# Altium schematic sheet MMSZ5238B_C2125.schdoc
size 127 x 101 mm
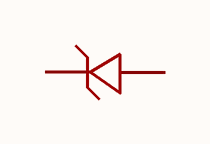
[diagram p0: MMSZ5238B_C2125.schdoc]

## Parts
Q?  mmsz5238b  [SOD-123_L2.8-W1.8-LS3.7-RD]  (value not drawn)

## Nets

Not connected (* = marked no-connect by the designer): Q? 1(K) 2(A)

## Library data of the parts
Q? = mmsz5238b: 二极管配置:1个独立式;稳压值(标称值):8.7V;稳压值(范围值):8.27V~9.14V;耗散功率(Pd):350mW;; Manufacturer: CJ(江苏长电/长晶); Symbol: MMSZ5238B_C2125; AddInBom: yes; ModelId: 7884390a25fb4c08947731ebfba7e3f8; ModelTransform: 144.8816,62.992,0,0,0,0,0,0,0; Diode Configuration: 1个独立式; Zener Voltage(Nom): 8.7V; Reverse Leakage Current (Ir): 3uA; Pd - Power Dissipation: 350mW; Impedance(Zzt): 8Ω; Impedance(Zzk): 600Ω; Operating Junction Temperature Range: -65℃~+150℃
